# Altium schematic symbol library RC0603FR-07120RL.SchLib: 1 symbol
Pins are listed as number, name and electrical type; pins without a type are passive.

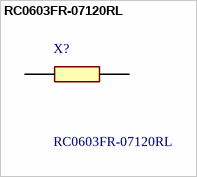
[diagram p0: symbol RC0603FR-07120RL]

## RC0603FR-07120RL
designator X?
YAGEO (PHYCOMP) - RC0603FR-07120RL - RES, THICK FILM, 120R, 1%, 0.1W, 0603; Manufacturer_Name: Yageo Group; Geometry.Height: 0.55mm
footprint RESC1608X55N
pins: 1, 2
